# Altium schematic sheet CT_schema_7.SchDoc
size 287 x 160 mm
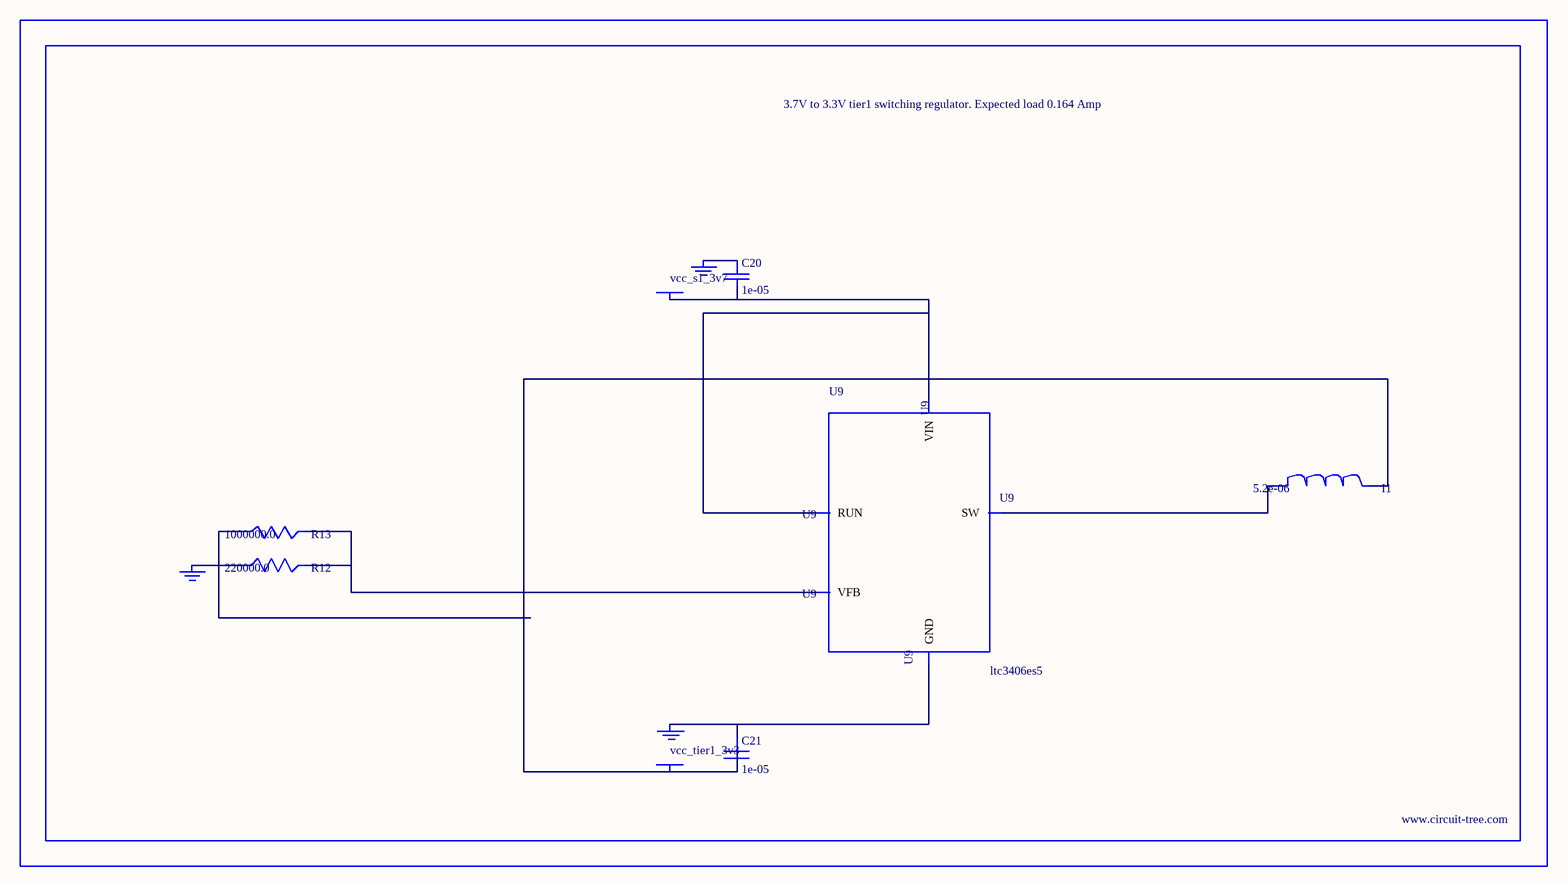
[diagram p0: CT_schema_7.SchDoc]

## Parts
BORDER6  (no value)
C20  1e-05  [C0805]
C21  1e-05  [C0805]
GND_INSTANCE_6_0  (no value)
GND_INSTANCE_6_1  (no value)
GND_INSTANCE_6_2  (no value)
I1  5.2e-06  [DR1040]
POWER_INSTANCE_6_0  vcc_tier1_3v3
POWER_INSTANCE_6_1  vcc_s1_3v7
R12  220000.0  [R0603]
R13  1000000.0  [R0603]
U9  ltc3406es5  [TSOT-23-5]

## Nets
NetC20_1: C20.1 GND_INSTANCE_6_1.0(GND)
NetC20_2: C20.2 POWER_INSTANCE_6_1.0(PWR) U9.1(RUN) U9.4(VIN)
NetC21_1: C21.1 GND_INSTANCE_6_0.0(GND) U9.2(GND)
NetC21_2: C21.2 I1.2 POWER_INSTANCE_6_0.0(PWR) R13.1
NetGND_INSTANCE_6_2_0: GND_INSTANCE_6_2.0(GND) R12.1
NetI1_1: I1.1 U9.3(SW)
NetR12_2: R12.2 R13.2 U9.5(VFB)

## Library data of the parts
BORDER6 = BORDER_PAGE6
C20 C21 = C0805C106K8RACTU
GND_INSTANCE_6_0-GND_INSTANCE_6_2 = GND
I1 = DR1040-5R2-R
POWER_INSTANCE_6_0 POWER_INSTANCE_6_1 = PWR
R12 = RC0603JR-07220KL
R13 = RC0603JR-071ML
